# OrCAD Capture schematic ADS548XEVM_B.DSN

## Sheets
1 SH 1 - Analog In: size B; title: ADS548X Evaluation Module; rev: B; note: ADS548XEVM-SCH
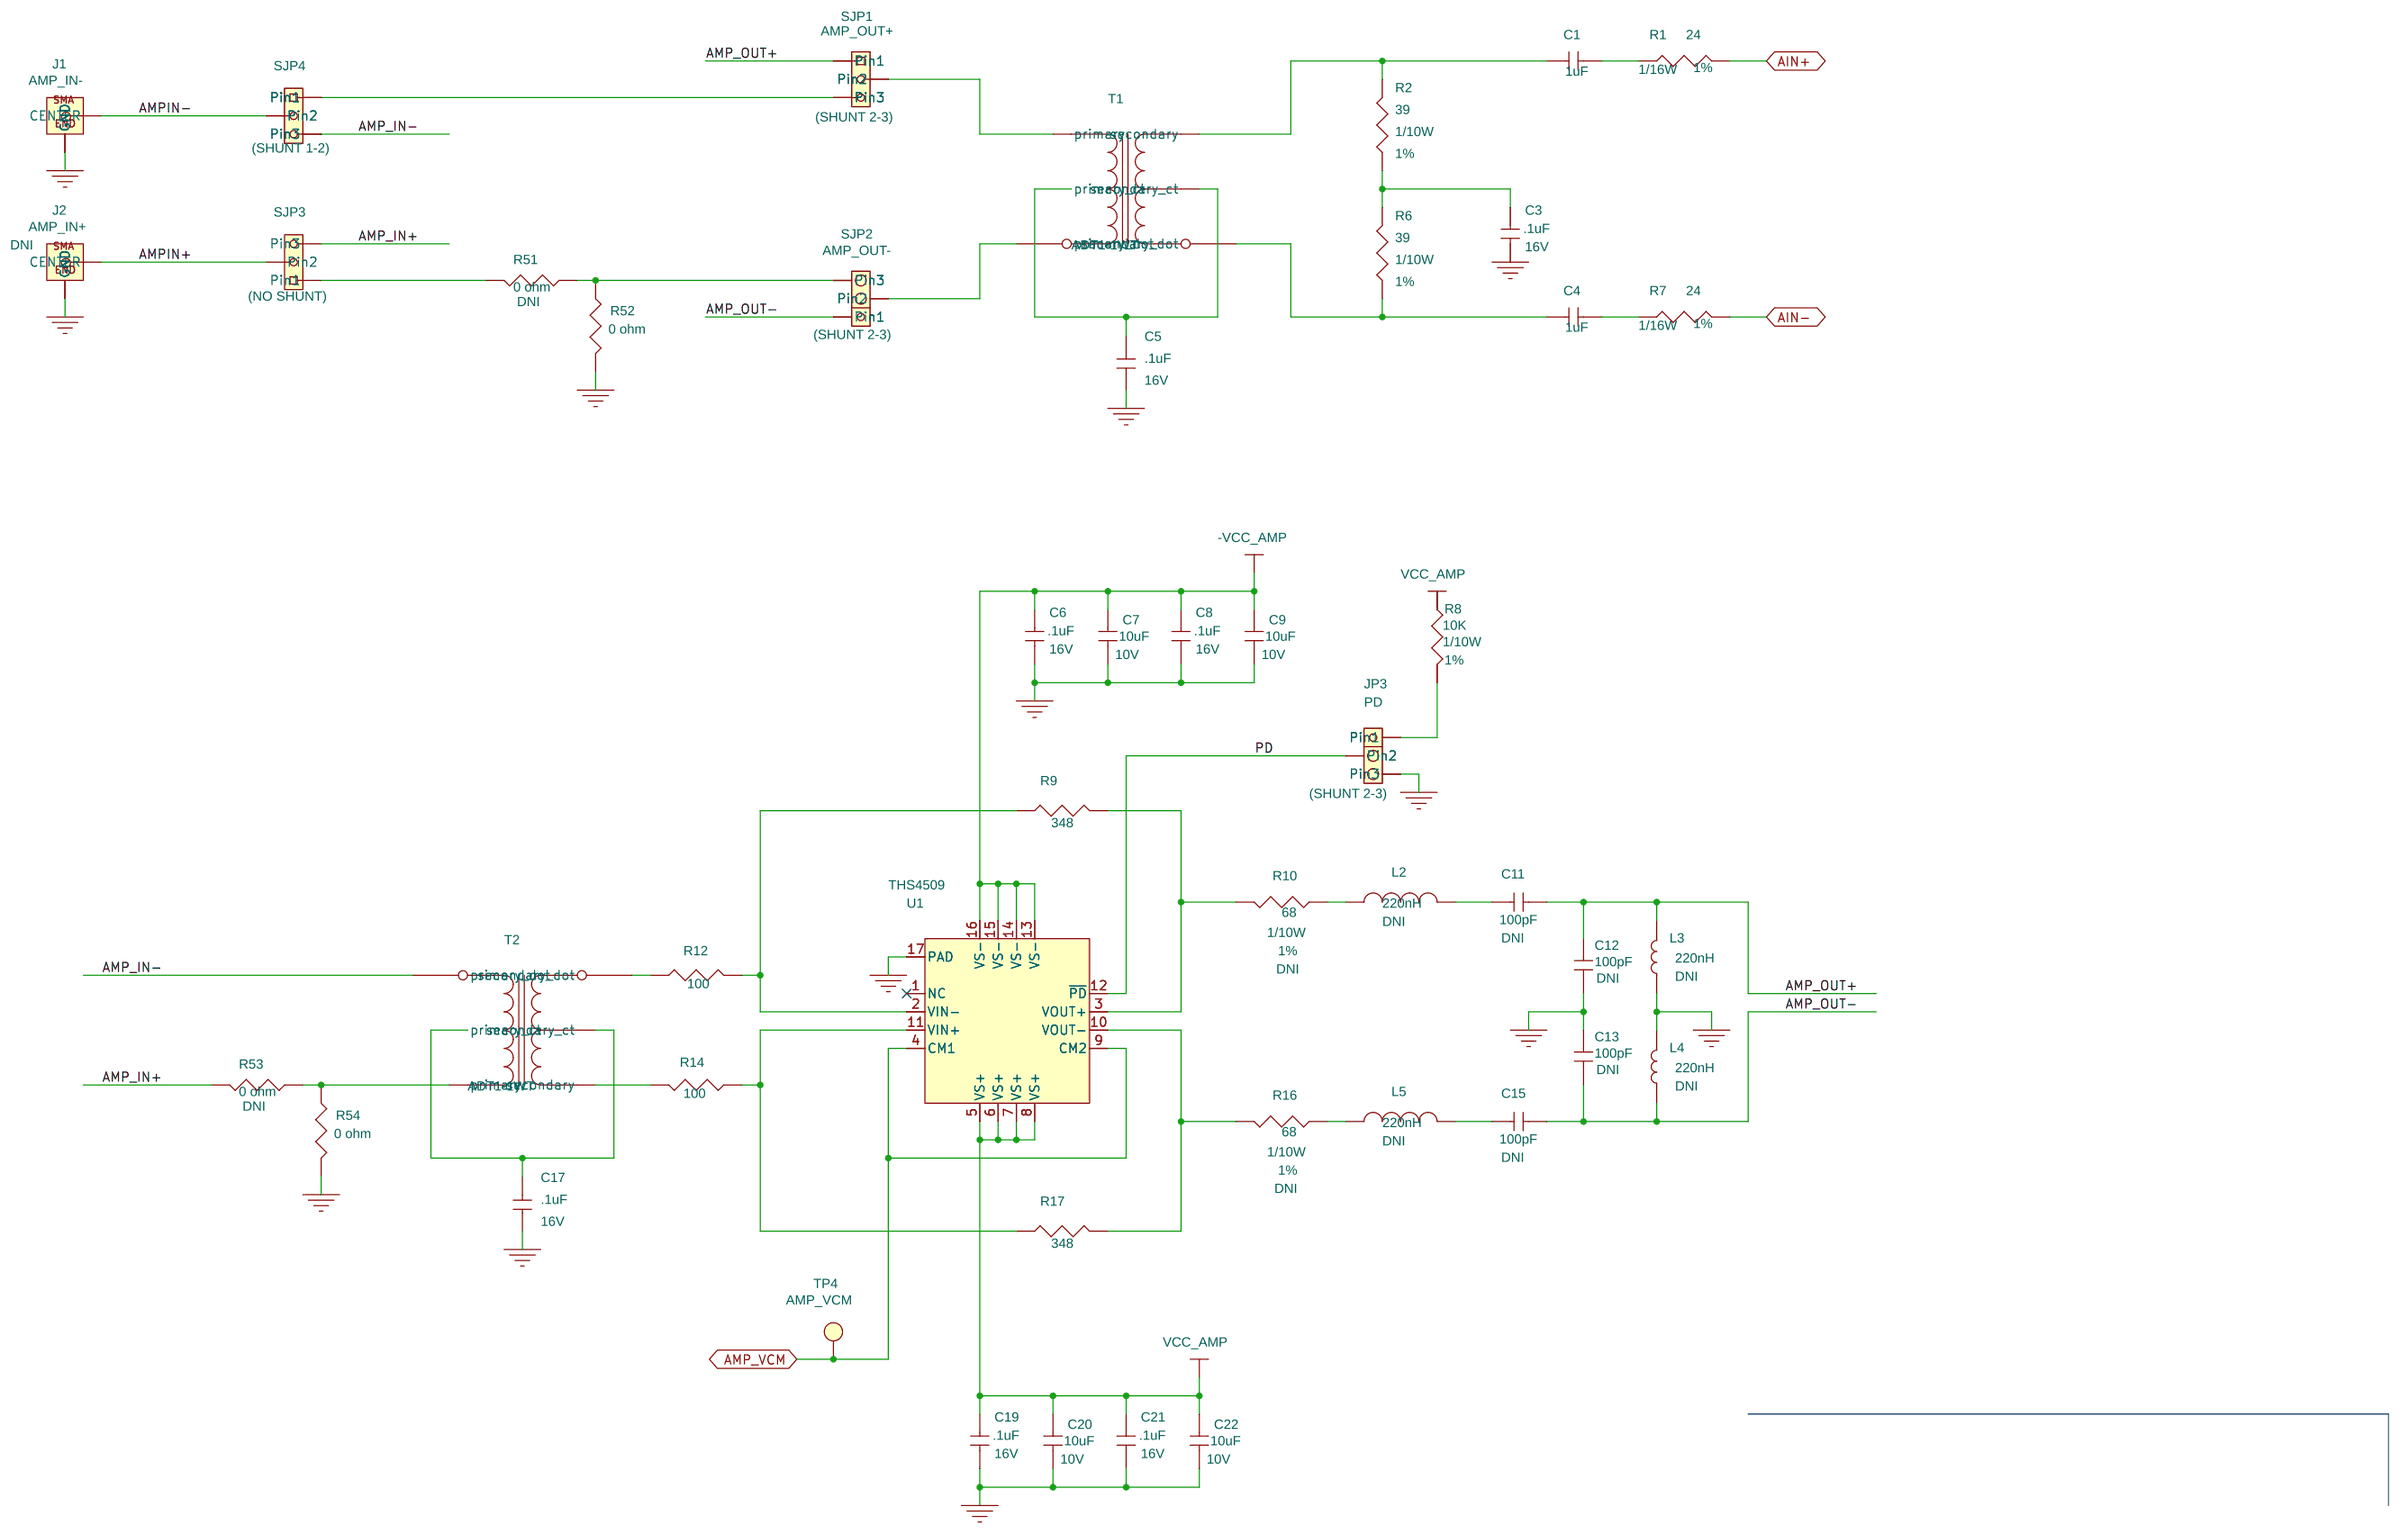
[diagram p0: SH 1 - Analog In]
2 SH 2 - ADC: size B
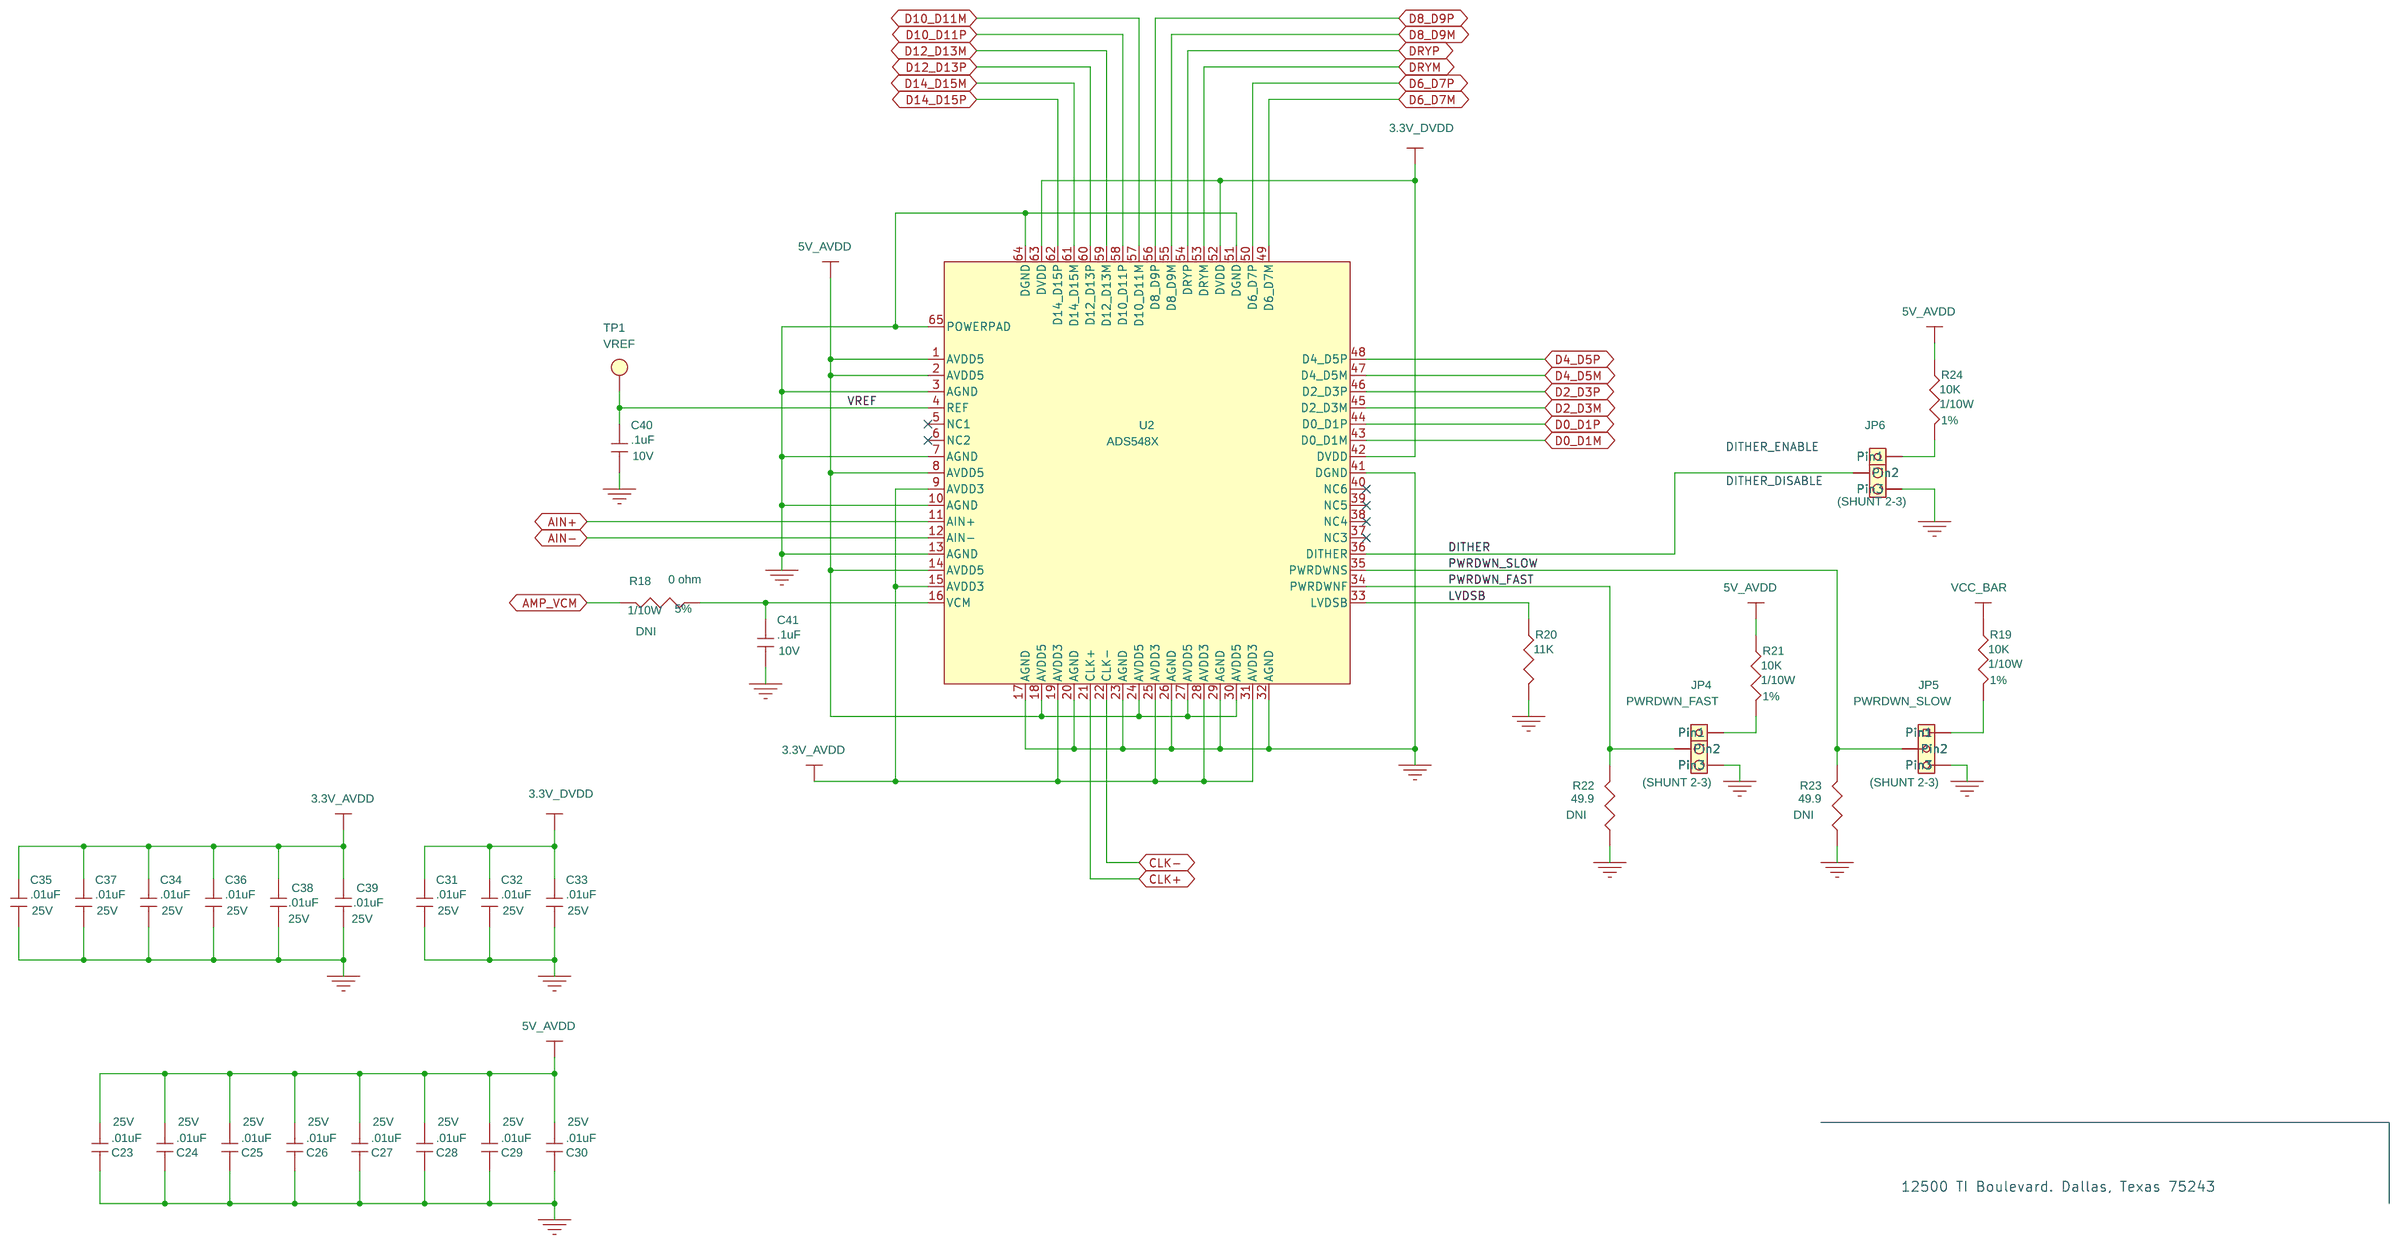
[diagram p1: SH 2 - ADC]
3 SH 3 - Output: size B
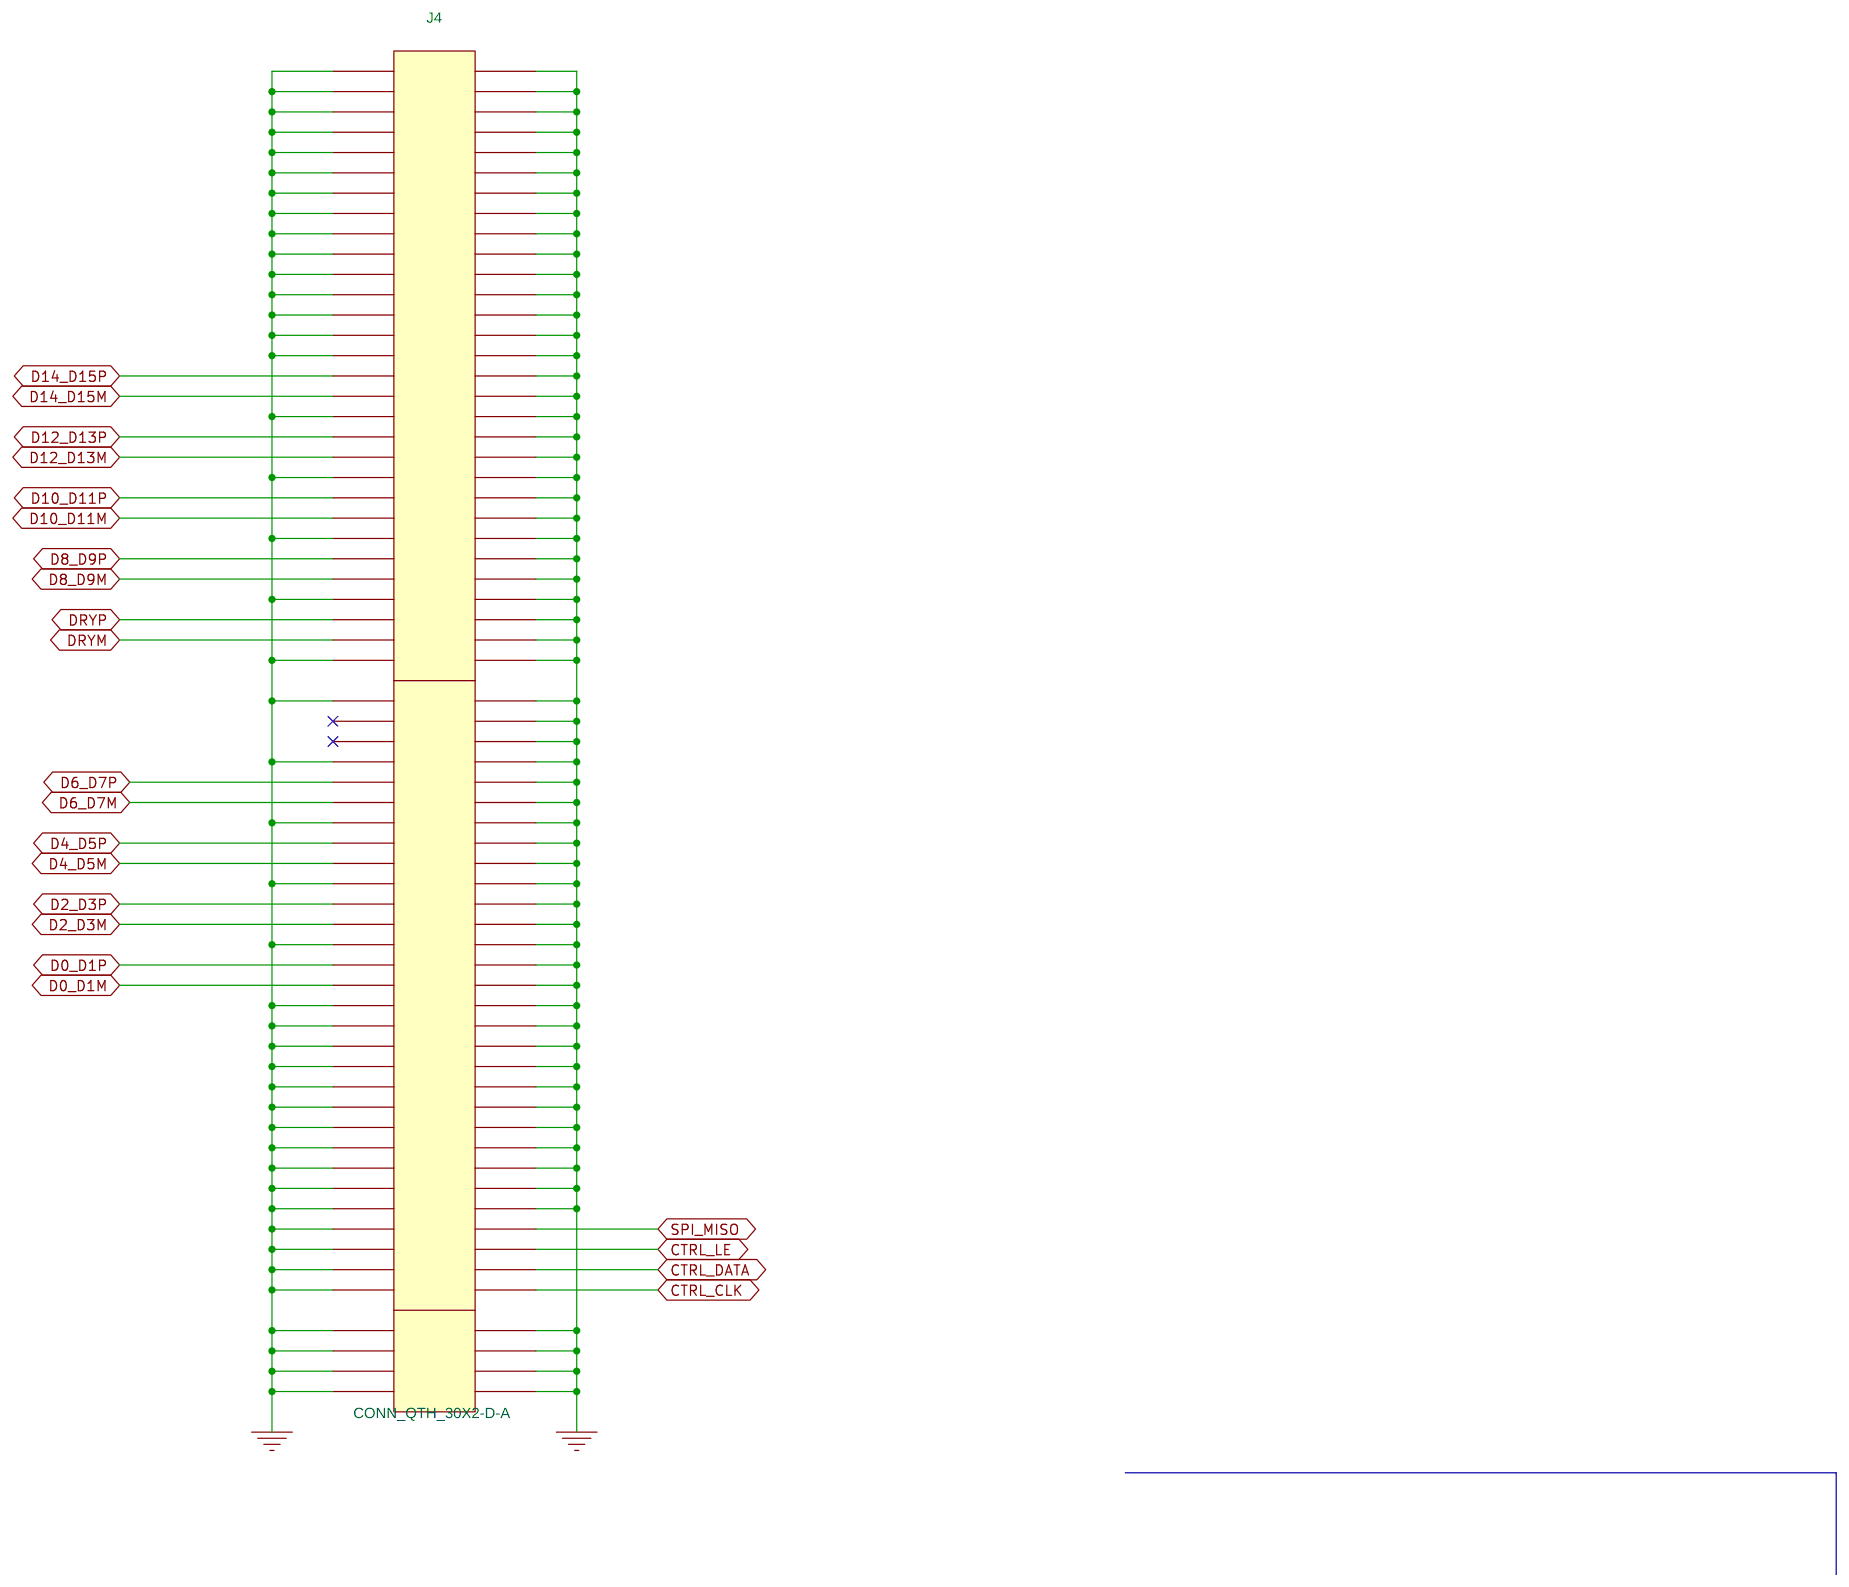
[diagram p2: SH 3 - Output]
4 SH 4 - Power Supplies: size B
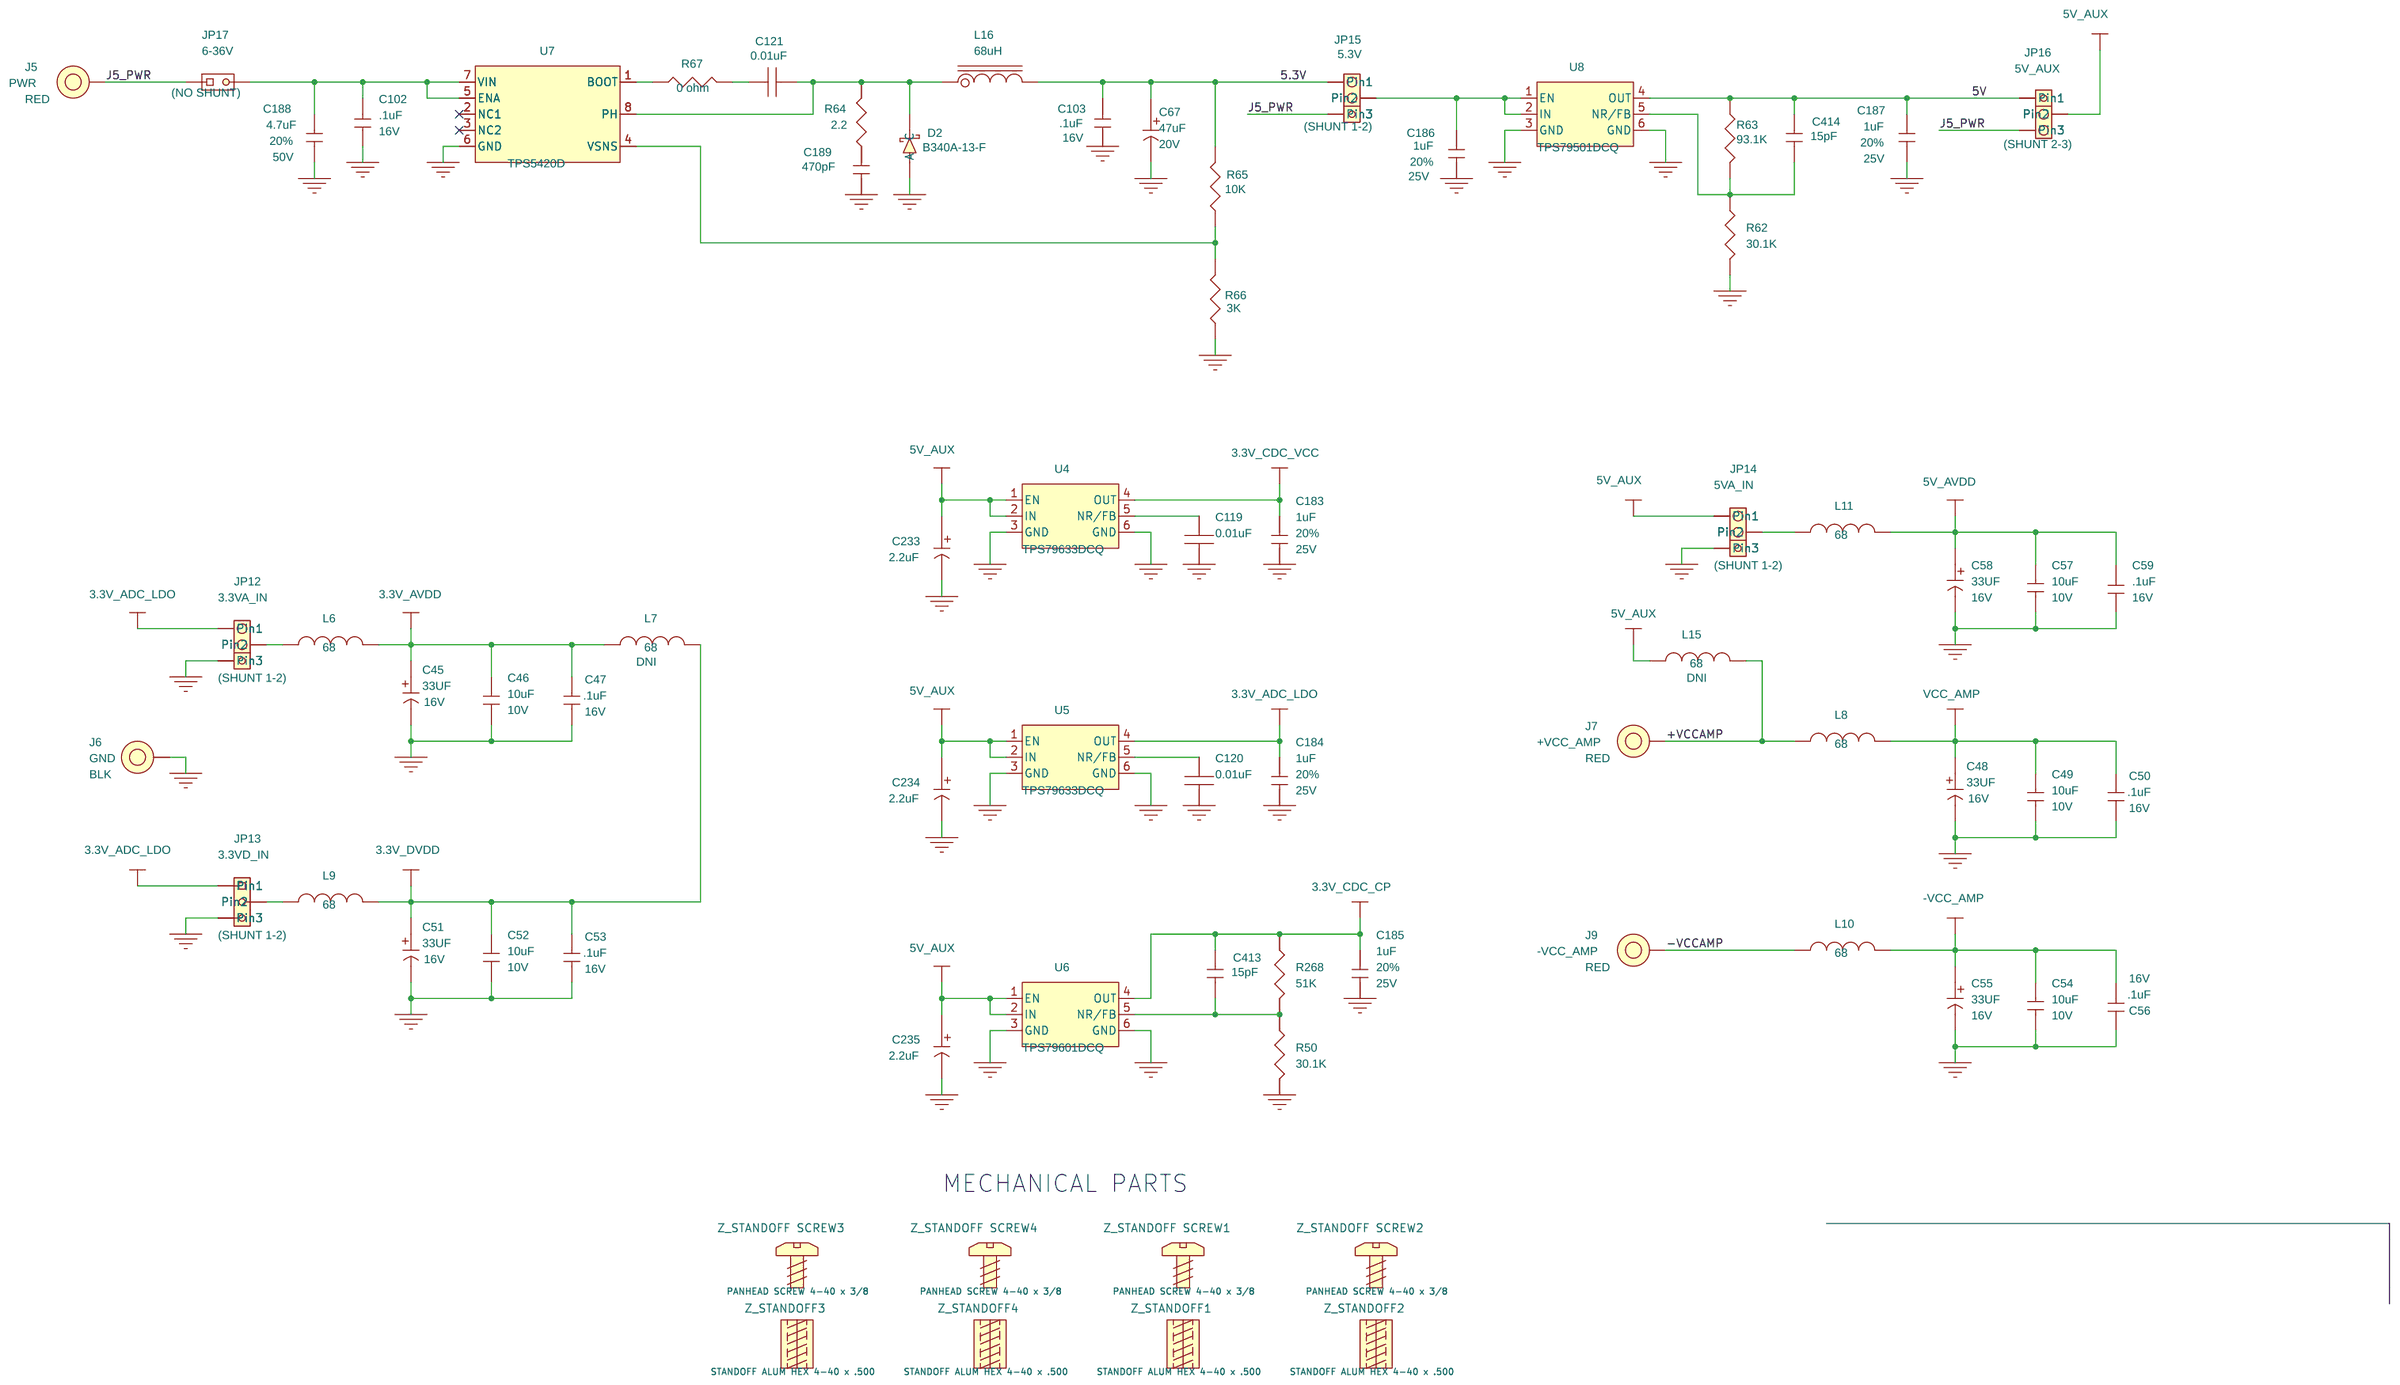
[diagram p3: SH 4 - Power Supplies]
5 SH 5 - Clock In: size B
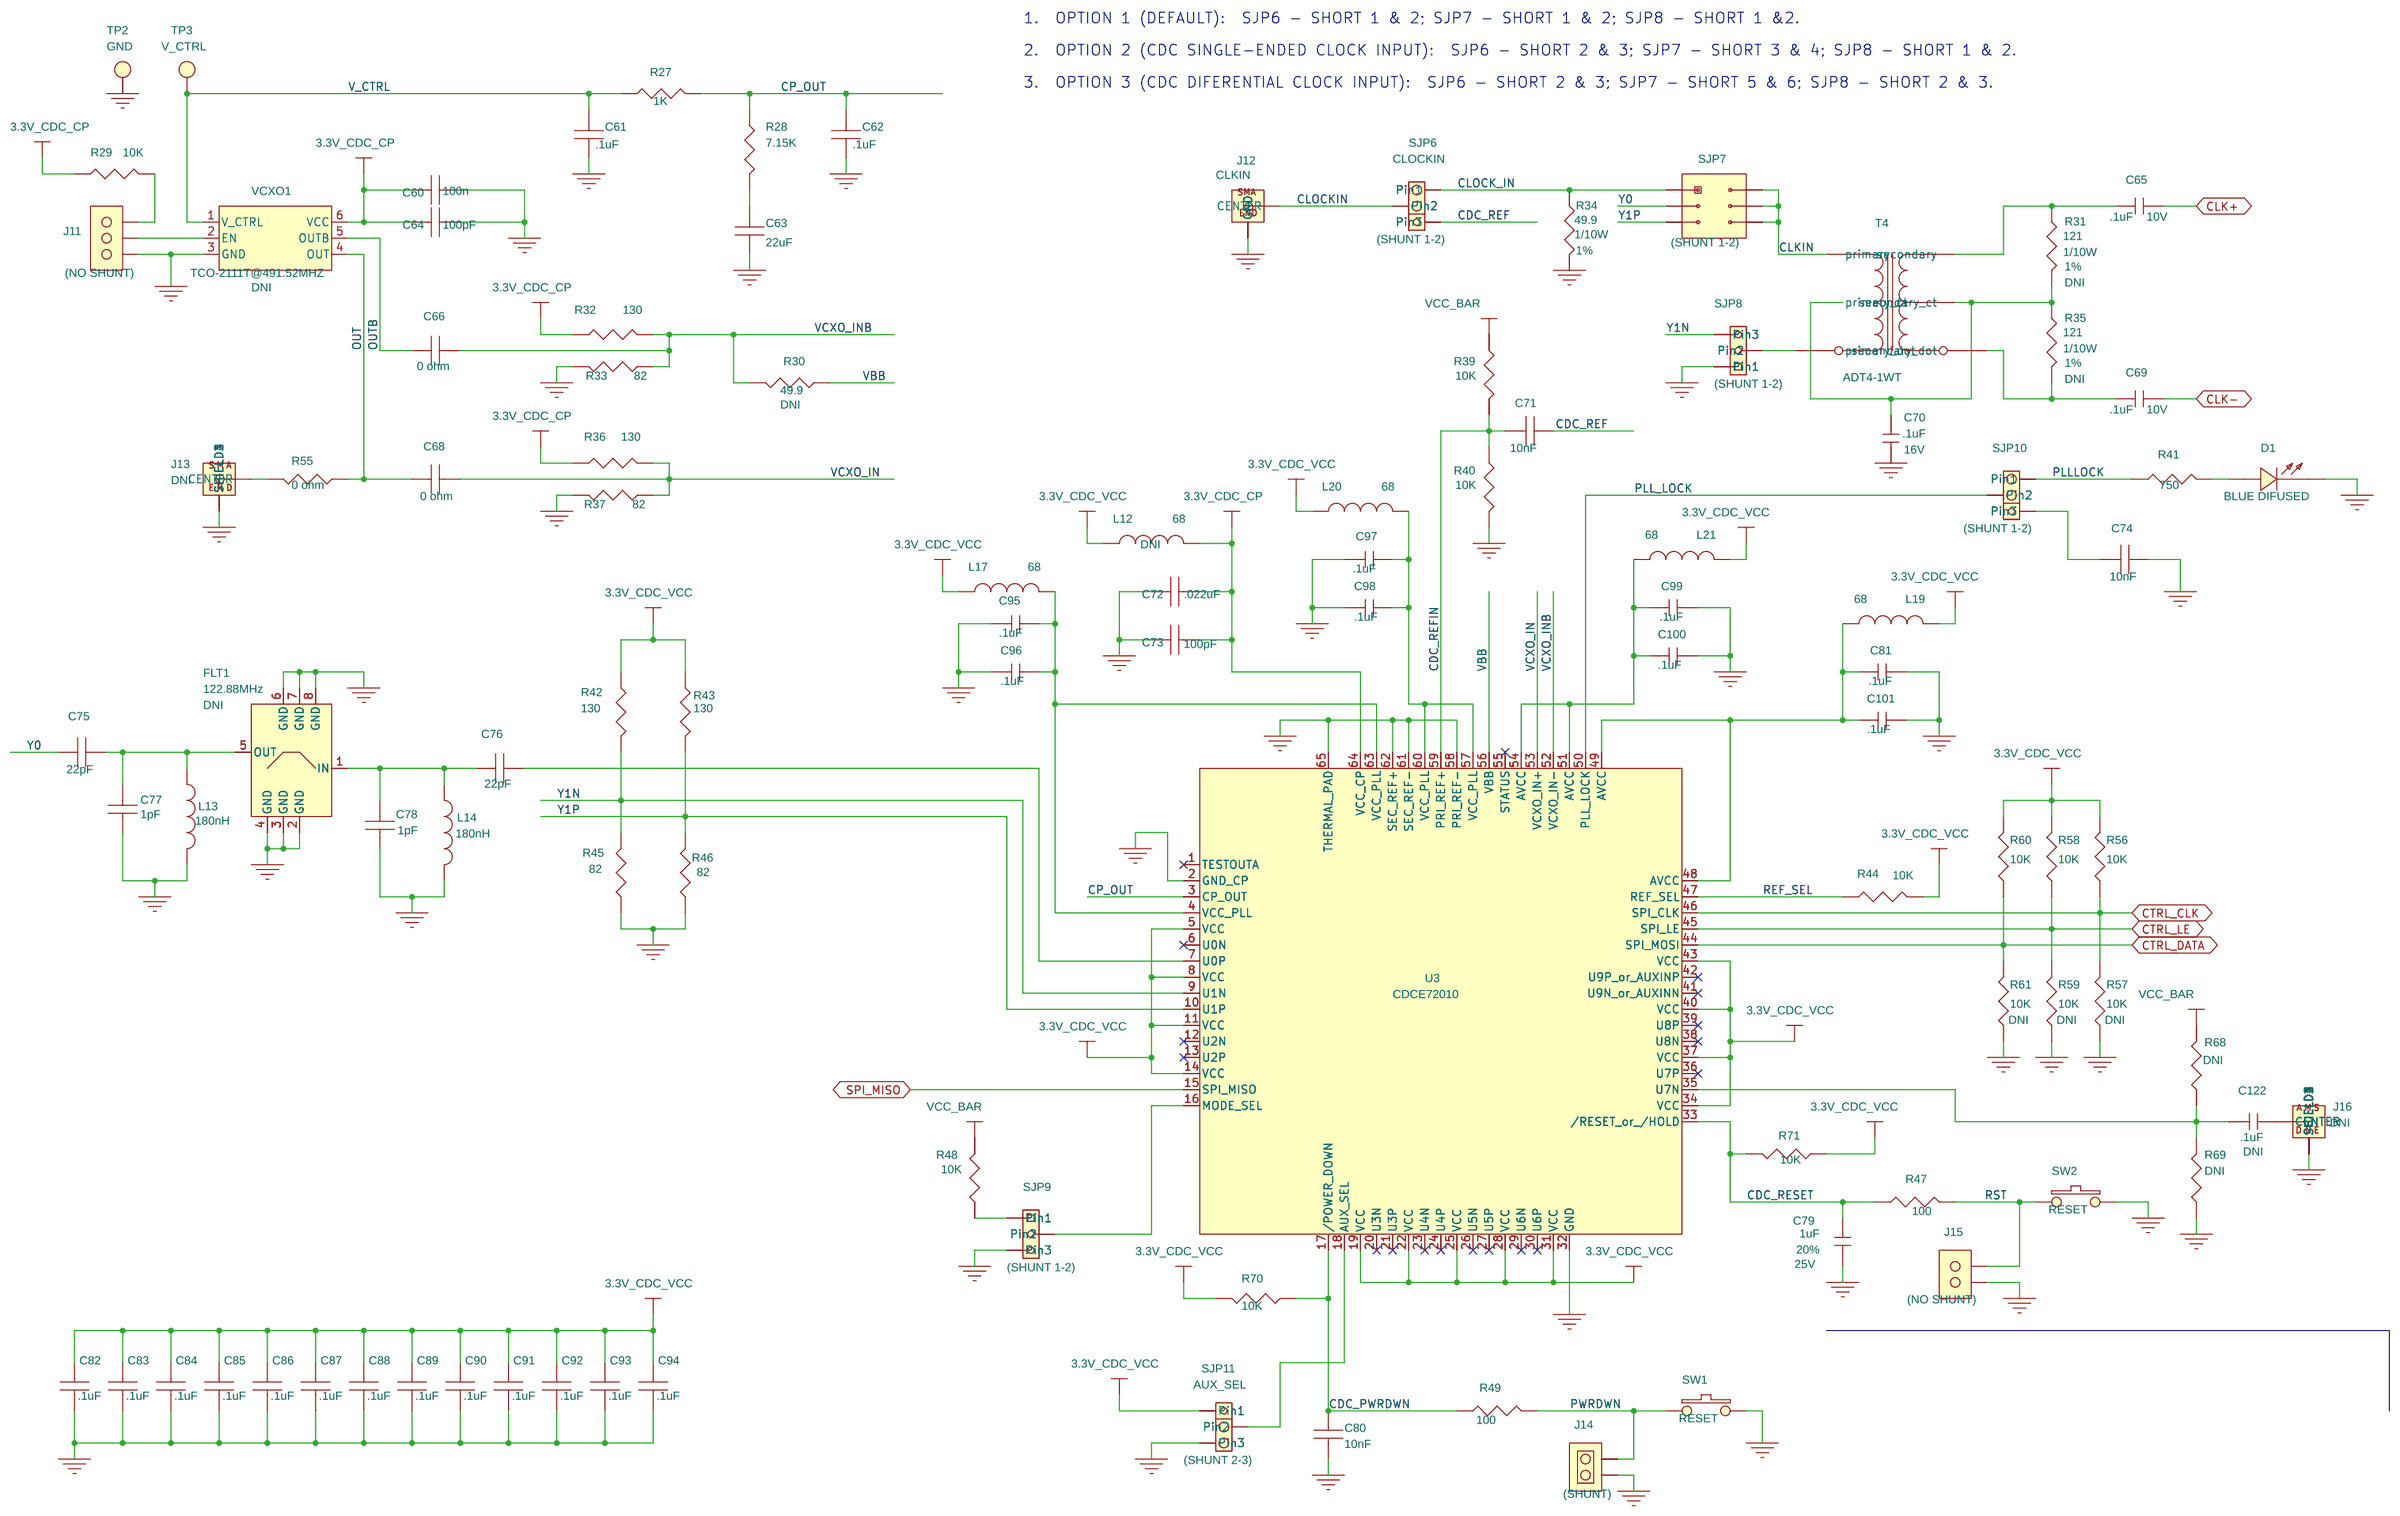
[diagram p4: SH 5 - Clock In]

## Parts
sheet SH 1 - Analog In
C1  1uF  [0603]
C3  .1uF  [0603]
C4  1uF  [0603]
C5  .1uF  [0603]
C6  .1uF  [0603]
C7  10uF  [0805]
C8  .1uF  [0603]
C9  10uF  [0805]
C11  100pF  [0603]
C12  100pF  [0603]
C13  100pF  [0603]
C15  100pF  [0603]
C17  .1uF  [0603]
C19  .1uF  [0603]
C20  10uF  [0805]
C21  .1uF  [0603]
C22  10uF  [0805]
J1  SMA_END_JACK_RND  [SMA_SMEL_250x215]
J2  SMA_END_JACK_RND  [SMA_SMEL_250x215]
JP3  HEADER_1x3_100_430L  [HDR_THVT_1x3_100_M]
L2  220nH  [1206]
L3  220nH  [0603]
L4  220nH  [0603]
L5  220nH  [1206]
R1  24  [0603]
R2  39  [0603]
R6  39  [0603]
R7  24  [0603]
R8  10K  [0603]
R9  348  [0603]
R10  68  [0603]
R12  100  [0603]
R14  100  [0603]
R16  68  [0603]
R17  348  [0603]
R51  0 ohm  [0603]
R52  0 ohm  [0603]
R53  0 ohm  [0603]
R54  0 ohm  [0603]
SJP1  JUMPER_1x3_SMT  [SMD_BRIDGE_1x3_0603]
SJP2  JUMPER_1x3_SMT  [SMD_BRIDGE_1x3_0603]
SJP3  JUMPER_1x3_SMT  [SMD_BRIDGE_1x3_0603]
SJP4  JUMPER_1x3_SMT  [SMD_BRIDGE_1x3_0603]
T1  ADT1-1WT  [TRANS_SMVT_CD542_6]
T2  ADT1-1WT  [TRANS_SMVT_CD542_6]
TP4  Test Point Black  [TP_THVT_060_RND]
U1  THS4509  [QFN_16_124x124_pwrpad]
Z_SH-H1  SHUNT-HEADER
Z_SH-J1  SHUNT-JUMPER-0603
Z_SH-J2  SHUNT-JUMPER-0603
Z_SH-J4  SHUNT-JUMPER-0603
sheet SH 2 - ADC
C23  .01uF  [0402]
C24  .01uF  [0402]
C25  .01uF  [0402]
C26  .01uF  [0402]
C27  .01uF  [0402]
C28  .01uF  [0402]
C29  .01uF  [0402]
C30  .01uF  [0402]
C31  .01uF  [0402]
C32  .01uF  [0402]
C33  .01uF  [0402]
C34  .01uF  [0402]
C35  .01uF  [0402]
C36  .01uF  [0402]
C37  .01uF  [0402]
C38  .01uF  [0402]
C39  .01uF  [0402]
C40  .1uF  [0402]
C41  .1uF  [0402]
JP4  HEADER_1x3_100_430L  [HDR_THVT_1x3_100_M]
JP5  HEADER_1x3_100_430L  [HDR_THVT_1x3_100_M]
JP6  HEADER_1x3_100_430L  [HDR_THVT_1x3_100_M]
R18  0 ohm  [0603]
R19  10K  [0603]
R20  11K  [0603]
R21  10K  [0603]
R22  49.9  [0603]
R23  49.9  [0603]
R24  10K  [0603]
TP1  TP_THVT_060_RND-WHT  [TP_THVT_060_RND]
U2  ADS548X  [QFN64]
Z_SH-H2  SHUNT-HEADER
Z_SH-H3  SHUNT-HEADER
Z_SH-H8  SHUNT-HEADER
sheet SH 3 - Output
J4  CONN_QTH_30X2-D-A  [conn_QTH_30X2-D-A]
sheet SH 4 - Power Supplies
C45  33UF  [TANT_B]
C46  10uF  [0805]
C47  .1uF  [0603]
C48  33UF  [TANT_B]
C49  10uF  [0805]
C50  .1uF  [0603]
C51  33UF  [TANT_B]
C52  10uF  [0805]
C53  .1uF  [0603]
C54  10uF  [0805]
C55  33UF  [TANT_B]
C56  .1uF  [0603]
C57  10uF  [0805]
C58  33UF  [TANT_B]
C59  .1uF  [0603]
C67  47uF  [TANT_E]
C102  .1uF  [0603]
C103  .1uF  [0603]
C119  0.01uF  [0402]
C120  0.01uF  [0402]
C121  0.01uF  [0402]
C183  1uF  [0603]
C184  1uF  [0603]
C185  1uF  [0603]
C186  1uF  [0603]
C187  1uF  [0603]
C188  4.7uF  [1206]
C189  470pF  [0603]
C233  2.2uF  [1206]
C234  2.2uF  [1206]
C235  2.2uF  [1206]
C413  15pF  [0402]
C414  15pF  [0402]
D2  B340A-13-F  [DIODE_SM_DO_214AC]
J5  RED  [JACK_THVT_BANANA_500DIA]
J6  BLK  [JACK_THVT_BANANA_500DIA]
J7  RED  [JACK_THVT_BANANA_500DIA]
J9  RED  [JACK_THVT_BANANA_500DIA]
JP12  HEADER_1x3_100_430L  [HDR_THVT_1x3_100_M]
JP13  HEADER_1x3_100_430L  [HDR_THVT_1x3_100_M]
JP14  HEADER_1x3_100_430L  [HDR_THVT_1x3_100_M]
JP15  HEADER_1x3_100_430L  [HDR_THVT_1x3_100_M]
JP16  HEADER_1x3_100_430L  [HDR_THVT_1x3_100_M]
JP17  HEADER_1x2_100_430L  [HDR_THVT_1x2_100_M]
L6  68  [1206]
L7  68  [1206]
L8  68  [1206]
L9  68  [1206]
L10  68  [1206]
L11  68  [1206]
L15  68  [1206]
L16  68uH  [IND_SM_MSS1038]
R50  30.1K  [0603]
R62  30.1K  [0603]
R63  93.1K  [0603]
R64  2.2  [0603]
R65  10K  [0603]
R66  3K  [0603]
R67  0 ohm  [0603]
R268  51K  [0402]
U4  TPS79633DCQ  [SOT_223_6_TG]
U5  TPS79633DCQ  [SOT_223_6_TG]
U6  TPS79601DCQ  [SOT_223_6_TG]
U7  TPS5420D  [SOIC_8_197x157_50]
U8  TPS79501DCQ  [SOT_223_6_TG]
Z_SH-H4  SHUNT-HEADER
Z_SH-H5  SHUNT-HEADER
Z_SH-H6  SHUNT-HEADER
Z_SH-H9  SHUNT-HEADER
Z_SH-H10  SHUNT-HEADER
Z_STANDOFF1  STANDOFF ALUM HEX 4-40 x .500
Z_STANDOFF2  STANDOFF ALUM HEX 4-40 x .500
Z_STANDOFF3  STANDOFF ALUM HEX 4-40 x .500
Z_STANDOFF4  STANDOFF ALUM HEX 4-40 x .500
Z_STANDOFF SCREW1  PANHEAD SCREW 4-40 x 3/8
Z_STANDOFF SCREW2  PANHEAD SCREW 4-40 x 3/8
Z_STANDOFF SCREW3  PANHEAD SCREW 4-40 x 3/8
Z_STANDOFF SCREW4  PANHEAD SCREW 4-40 x 3/8
sheet SH 5 - Clock In
C60  100n  [0603]
C61  .1uF  [0603]
C62  .1uF  [0603]
C63  22uF  [0805]
C64  100pF  [0603]
C65  .1uF  [0402]
C66  0 ohm  [0603]
C68  0 ohm  [0603]
C69  .1uF  [0402]
C70  .1uF  [0603]
C71  10nF  [0603]
C72  .022uF  [0402]
C73  100pF  [0603]
C74  10nF  [0603]
C75  22pF  [0603]
C76  22pF  [0603]
C77  1pF  [0603]
C78  1pF  [0603]
C79  1uF  [0603]
C80  10nF  [0603]
C81  .1uF  [0201]
C82  .1uF  [0201]
C83  .1uF  [0201]
C84  .1uF  [0201]
C85  .1uF  [0201]
C86  .1uF  [0201]
C87  .1uF  [0201]
C88  .1uF  [0201]
C89  .1uF  [0201]
C90  .1uF  [0201]
C91  .1uF  [0201]
C92  .1uF  [0201]
C93  .1uF  [0201]
C94  .1uF  [0201]
C95  .1uF  [0201]
C96  .1uF  [0201]
C97  .1uF  [0201]
C98  .1uF  [0201]
C99  .1uF  [0201]
C100  .1uF  [0201]
C101  .1uF  [0201]
C122  .1uF  [0402]
D1  BLUE DIFUSED  [DIODE_SM_HSMN_C170]
FLT1  122.88MHz  [FILTER_8_SM_150x150]
J11  HMTSW-103-07-G-S-.240  [HDR_THVT_1x3_100_M]
J12  SMA_END_JACK_RND  [SMA_SMEL_250x215]
J13  TI_SILKTEXT  [SMA_THVT_320x320]
J14  HMTSW-102-07-G-S-.240  [HDR_THVT_1x2_100_M]
J15  HMTSW-102-07-G-S-.240  [HDR_THVT_1x2_100_M]
J16  TI_SILKTEXT  [SMA_THVT_320x320]
L12  68  [1206]
L13  180nH  [0603]
L14  180nH  [0603]
L17  68  [1206]
L19  68  [1206]
L20  68  [1206]
L21  68  [1206]
R27  1K  [0603]
R28  7.15K  [0603]
R29  10K  [0603]
R30  49.9  [0603]
R31  121  [0603]
R32  130  [0603]
R33  82  [0603]
R34  49.9  [0603]
R35  121  [0603]
R36  130  [0603]
R37  82  [0603]
R39  10K  [0603]
R40  10K  [0603]
R41  750  [0603]
R42  130  [0603]
R43  130  [0603]
R44  10K  [0603]
R45  82  [0603]
R46  82  [0603]
R47  100  [0603]
R48  10K  [0603]
R49  100  [0603]
R55  0 ohm  [0603]
R56  10K  [0603]
R57  10K  [0603]
R58  10K  [0603]
R59  10K  [0603]
R60  10K  [0603]
R61  10K  [0603]
R68  10K  [0603]
R69  10K  [0603]
R70  10K  [0603]
R71  10K  [0603]
SJP6  JUMPER_1x3_SMT  [SMD_BRIDGE_1x3_0603]
SJP7  JUMPER_3X2_SMT  [SMD_BRIDGE_2x3_0603]
SJP8  JUMPER_1x3_SMT  [SMD_BRIDGE_1x3_0603]
SJP9  JUMPER_1x3_SMT  [SMD_BRIDGE_1x3_0603]
SJP10  JUMPER_1x3_SMT  [SMD_BRIDGE_1x3_0603]
SJP11  JUMPER_1x3_SMT  [SMD_BRIDGE_1x3_0603]
SW1  RESET  [SW_THVT_SPST_PTS635SL43]
SW2  RESET  [SW_THVT_SPST_PTS635SL43]
T4  ADT4-1WT  [TRANS_SMVT_CD542_6]
TP2  TP_THVT_060_RND-WHT  [TP_THVT_060_RND]
TP3  TP_THVT_060_RND-WHT  [TP_THVT_060_RND]
U3  CDCE72010  [QFN64]
VCXO1  TCO-2111T@491.52MHZ  [VCXO_6_CUSTOM2]
Z_SH-H7  SHUNT-HEADER
Z_SH-J5  SHUNT-JUMPER-0603
Z_SH-J6  SHUNT-JUMPER-0603
Z_SH-J7  SHUNT-JUMPER-0603
Z_SH-J8  SHUNT-JUMPER-0603
Z_SH-J9  SHUNT-JUMPER-0603
Z_SH-J10  SHUNT-JUMPER-0603

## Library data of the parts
C1 C4 = CAP0603: Manufacturer: Panasonic; Mfr_Name: Panasonic; Mfr_Part_Number: ECJ-1VB1C105K; PART_NUMBER: ECJ-1VB1A105K; TOL: 10%; Voltage: 10V
C3 C5 C6 C17 C19 C21 = CAP0603: Manufacturer: Panasonic; Mfr_Name: Panasonic; Mfr_Part_Number: ECJ-1VB1C104K; PART_NUMBER: ECJ-1VB1C104K; TOL: 10%; Voltage: 16V
C7 C9 C20 C22 C46 C49 C52 C54 C57 = CAP0201: Manufacturer: Panasonic; Mfr_Name: Panasonic; Mfr_Part_Number: ECJ-4YB1C106K; PART_NUMBER: ECJ-2FB1A106K; TOL: 10%; VOLTAGE: 10V
C8 = CAP0603: Manufacturer: Panasonic; Mfr_Name: Panasonic; Mfr_Part_Number: ECJ-1VB1C104K; PART_NUMBER: ECJ-1VB1C104K; TOL: 10%; Voltage: 16V; Wattage: 1/10W
C11-C13 C15 = CAP0603: Mfr_Name: Murata; Mfr_Part_Number: GQM1885C1H101JB01D_DNI; Note: DNI
J1 = SMA-END_JACK_142-0711-821_ROUND: TI_Silktext: AMP_IN-
J2 = SMA-END_JACK_142-0711-821_ROUND: Mfr_Part_Number: 142-0711-821_DNI; Note: DNI; TI_Silktext: AMP_IN+
JP3 = JUMPER_1x3_100: Note: (SHUNT 2-3); TI_Silktext: PD
L2 L5 = IND1206: Manufacturer: API Delavan Inc; Mfr_Name: Coilcraft; Mfr_Part_Number: 1206CS-221X-LB_DNI; Note: DNI
L3 L4 = IND0603: Mfr_Name: Coilcraft; Mfr_Part_Number: 0603CS-R22X-LU_DNI; Note: DNI; TOL: 2%
R1 R7 = RES0603: Manufacturer: Panasonic; Mfr_Name: Panasonic; Mfr_Part_Number: ERJ-3GEYJ240V; PART_NUMBER: ERJ-3GEYJ240V; TOL: 1%; Wattage: 1/16W
R2 R6 = RES0603: Manufacturer: Panasonic; Mfr_Name: Panasonic; Mfr_Part_Number: RC0603FR-0739RL; TOL: 1%; Wattage: 1/10W
R8 R19 R21 R24 = RES0603: Manufacturer: Panasonic; Mfr_Name: Panasonic; Mfr_Part_Number: ERJ-3EKF1002V; PART_NUMBER: ERJ-3EKF1002V; TOL: 1%; Wattage: 1/10W
R9 R17 = R: Manufacturer: Panasonic; PART_NUMBER: ERJ-3EKF3480V; TOL: 1%; Wattage: 1/10W
R10 R16 = RES0603: Manufacturer: Panasonic; Mfr_Name: Panasonic; Mfr_Part_Number: ERA-3AEB680V_DNI; Note: DNI; PART_NUMBER: ERA-3AEB680V; TOL: 1%; Wattage: 1/10W
R12 R14 = R: Manufacturer: Panasonic; PART_NUMBER: ERJ-3EKF1000V; TOL: 1%; Wattage: 1/10W
R51 R53 = R: CLASS: DISCRETE; GROUP: NOT INSTALLED; Manufacturer: DALE; Note: DNI; PART_NUMBER: CRCW06030000Z0EA_DNI; TOL: 5%; Wattage: 1/10W
R52 R54 R55 R67 = R: CLASS: DISCRETE; GROUP: NOT INSTALLED; Manufacturer: DALE; PART_NUMBER: CRCW06030000Z0EA; TOL: 5%; Wattage: 1/10W
SJP1 = SMD_JUMPER_0: Note: (SHUNT 2-3); TI_Silktext: AMP_OUT+
SJP2 = SMD_JUMPER_0: Note: (SHUNT 2-3); TI_Silktext: AMP_OUT-
SJP3 = SMD_JUMPER_0: Note: (NO SHUNT)
SJP4 = SMD_JUMPER_0: Note: (SHUNT 1-2)
T1 T2 = XFMR_6_ADT4-1WT: Manufacturer: Mini Circuits
TP4 = T_POINT_R: Manufacturer: Keystone; PART_NUMBER: 5001; TI_Silktext: AMP_VCM
U1 = THS4509_1: Manufacturer: TI; Note: TI Supplied; PART_NUMBER: THS4509RGTT
Z_SH-H1-Z_SH-H6 Z_SH-H8-Z_SH-H10 = SHUNT-HEADER
Z_SH-J1 Z_SH-J2 Z_SH-J4-Z_SH-J6 Z_SH-J8-Z_SH-J10 = SHUNT-JUMPER-0603
C23-C37 = CAP0402: Manufacturer: Panasonic; Mfr_Name: Panasonic; Mfr_Part_Number: ECJ-ZEB1A103K; PART_NUMBER: ECJ-0EB1E103K; TOL: +/-10%; Voltage: 25V
C38 C39 = CAP0201: Manufacturer: Panasonic; Mfr_Name: Panasonic; Mfr_Part_Number: ECJ-4YB1C106K; PART_NUMBER: ECJ-0EB1E103K; TOL: 10%; VOLTAGE: 25V
C40 C41 C65 C69 = CAP0402: Manufacturer: Panasonic; Mfr_Name: Panasonic; Mfr_Part_Number: ECJ-0EF1E104Z; PART_NUMBER: ECJ-0EB1A104K; TOL: 10%; Voltage: 10V
JP4 = JUMPER_1x3_100: Note: (SHUNT 2-3); TI_Silktext: PWRDWN_FAST
JP5 = JUMPER_1x3_100: Note: (SHUNT 2-3); TI_Silktext: PWRDWN_SLOW
JP6 = JUMPER_1x3_100: Note: (SHUNT 2-3); TI_Silktext: TI_Silktext
R18 = RES0805: Manufacturer: Panasonic; Mfr_Name: Panasonic; Mfr_Part_Number: ERJ-3GEY0R00V; Note: DNI; PART_NUMBER: ERJ-3GEY0R00V; TOL: 5%; Wattage: 1/10W
R20 = RES0603: Manufacturer: Panasonic; Mfr_Name: Panasonic; Mfr_Part_Number: ERJ-3EKF1102V; PART_NUMBER: ERJ-3EKF1102V; TOL: 1%; Wattage: 1/10W
R22 R23 R30 = RES0402: GROUP: Not Installed; Manufacturer: Panasonic; Mfr_Name: Panasonic; Mfr_Part_Number: ERJ-3EKF49R9V_DNI; Note: DNI; PART_NUMBER: ERJ-3EKF49R9V_DNI; TOL: 1%; Wattage: 1/10W
TP1 = TP_THVT_060_RND-WHT: TI_SILKTEXT: VREF
U2 = ENZO_8: Manufacturer: TI; Note: TI Supplied
J4 = SAMTEC_CONN_30X2-D-A: Manufacturer: Samtec; PART_NUMBER: QTH-060-02-F-D-A
C45 C48 C51 C55 C58 = CAP_POL-B: Manufacturer: AVX; Mfr_Name: Panasonic; Mfr_Part_Number: ECS-T1AX336R; PART_NUMBER: TPSB336K016R0350; TOL: 10%; Voltage: 16V
C47 C50 C53 C56 C59 C70 C102 C103 = CAP0603: Manufacturer: Panasonic; Mfr_Name: Panasosnic; Mfr_Part_Number: ECJ-1VB1C104K; PART_NUMBER: ECJ-1VB1C104K; TOL: 10%; Voltage: 16V
C67 = CAP_POL-B: Manufacturer: AVX; Mfr_Name: AVX; Mfr_Part_Number: TPSE476M020R0150; PART_NUMBER: TPSE476M020R0150; TOL: 10%; Voltage: 20V
C119-C121 = CAPACITOR_NP_4: CAP, CERAMIC, 0.01uF, 0402, 10%, 25VDC, X7R; Mfr_Name: Panasonic; Mfr_Part_Number: ECJ-0EB1E103K; TOL: 10%
C79 C183-C187 = CAP_NP_0: Mfr_Name: Panasonic; Mfr_Part_Number: ECJ-1V41E105M; TOL: 20%; VOLTAGE: 25V
C188 = CAP_NP_0: Mfr_Name: Murata; Mfr_Part_Number: GRM31CF51H475ZA01L; TOL: 20%; VOLTAGE: 50V
C189 = CAP_NP_0: Mfr_Name: Murata; Mfr_Part_Number: GRM188R71H471MA01D; TOL: 20%; VOLTAGE: 50V
C233-C235 = CAP_POL-B: Mfr_Name: Panasonic; Mfr_Part_Number: ECJ-HVB1A225K
C413 C414 = CAP_NP_0: Mfr_Name: Panasonic; Mfr_Part_Number: ECJ-0EC1H150J; TOL: 5%; VOLTAGE: 50V
D2 = DIODE_B340A-13-F
J5 = BANANA_JACK_RED: Manufacturer: SPC Technology; PART_NUMBER: 845-R; TI_Silktext: PWR
J6 = BANANA_JACK_BLK: Manufacturer: SPC Technology; PART_NUMBER: 845-B; TI_Silktext: GND
J7 = BANANA_JACK_RED: Manufacturer: SPC Technology; PART_NUMBER: 845-R; TI_Silktext: +VCC_AMP
J9 = BANANA_JACK_RED: Manufacturer: SPC Technology; PART_NUMBER: 845-R; TI_Silktext: -VCC_AMP
JP12 = JUMPER_1x3_100: Note: (SHUNT 1-2); TI_Silktext: 3.3VA_IN
JP13 = JUMPER_1x3_100: Note: (SHUNT 1-2); TI_Silktext: 3.3VD_IN
JP14 = JUMPER_1x3_100: Note: (SHUNT 1-2); TI_Silktext: 5VA_IN
JP15 = JUMPER_1x3_100: Note: (SHUNT 1-2); TI_Silktext: 5.3V
JP16 = JUMPER_1x3_100: Note: (SHUNT 2-3); TI_Silktext: 5V_AUX
JP17 = JUMPER_1x2_100: Note: (NO SHUNT); TI_Silktext: 6-36V
L6 L8-L11 L17 L19-L21 = IND1206: Manufacturer: Panasonic; Mfr_Name: Panasonic; Mfr_Part_Number: EXC-ML32A680U; PART_NUMBER: EXC-ML32A680U
L7 L12 L15 = IND1206: Manufacturer: Panasonic; Mfr_Name: Panasonic; Mfr_Part_Number: EXC-ML32A680U_DNI; Note: DNI; PART_NUMBER: EXC-ML32A680U_DNI
L16 = IND_MSS1038_SERIES
R50 R62 = R_4: Mfr_Name: Panasonic; Mfr_Part_Number: ERJ-3EKF3012V; TOL: 1%; VOLTAGE: 1/10W
R63 = R_4: Mfr_Name: Panasonic; Mfr_Part_Number: ERJ-3EKF9312V; TOL: 1%; VOLTAGE: 1/10W
R64 = R_4: Mfr_Name: Panasonic; Mfr_Part_Number: ERJ-3RQF2R2V; TOL: 1%; VOLTAGE: 1/10W
R29 R39 R40 R44 R48 R56 R58 R60 R65 R70 R71 = R: CLASS: DISCRETE; Manufacturer: DALE; PART_NUMBER: CRCW060310K0FKEA; TOL: 1%; Wattage: 1/10W
R66 = R: CLASS: DISCRETE; Manufacturer: Yageo; PART_NUMBER: RC0603FR-073KL; TOL: 1%; Wattage: 1/10W
R268 = R_4: Mfr_Name: Panasonic; Mfr_Part_Number: ERJ-S02F5102X; TOL: 1%
U4 U5 = TPS79633DCQ_1
U6 = TPS79601DCQ_2
U7 = TPS5420D
U8 = TPS79501DCQ_0
Z_STANDOFF1-Z_STANDOFF4 = STANDOFF
Z_STANDOFF SCREW1-Z_STANDOFF SCREW4 = SCREW-STANDOFF
C60-C62 = CAP_NP: CLASS: DISCRETE; Manufacturer: Panasonic; PART_NUMBER: ECJ-1VB1C104K; TOL: 10%; VOLTAGE: 16V
C63 = CAP_NP: CLASS: DISCRETE; Manufacturer: Panasonic; PART_NUMBER: ECJ-2FB0J226M; TOL: 20%; VOLTAGE: 6.3V
C64 C73 = CAP_NP: CLASS: DISCRETE; Manufacturer: Panasonic; PART_NUMBER: ECJ-1VC1H101J; TOL: 5%; VOLTAGE: 50V
C66 C68 = CAP_NP: CLASS: DISCRETE; Manufacturer: DALE; PART_NUMBER: CRCW06030000Z0EA; TOL: 5%; Wattage: 1/10W
C71 C74 C80 = CAP_NP: CLASS: DISCRETE; Manufacturer: AVX; PART_NUMBER: 06035C103KAZ2A; TOL: 10%; VOLTAGE: 50V
C72 = CAP_NP: CLASS: DISCRETE; Manufacturer: AVX Corporation; PART_NUMBER: 0402YC223KAT2A
C75 C76 = CAP_NP: Manufacturer: AVX; PART_NUMBER: 06033J220GBTTR; TOL: 2%; VOLTAGE: 25V
C77 C78 = CAP_NP: Manufacturer: Murata; PART_NUMBER: GQM1885C2A1R0CB01D; TOL: .25pF; VOLTAGE: 100V
C81 C95-C101 = CAP_NP_0: CLASS: DISCRETE; Manufacturer: Panasonic; PART_NUMBER: ECJ-ZEBFJ104K; TOL: 5%; VOLTAGE: 50V
C82-C94 = CAP_NP: CLASS: DISCRETE; Manufacturer: Panasonic; PART_NUMBER: ECJ-ZEBFJ104K; TOL: 5%; VOLTAGE: 50V
C122 = CAP_NP_0: Mfr_Name: Panasonic; Mfr_Part_Number: ECJ-0EB1C104K_DNI; Note: DNI; TOL: 10%; VOLTAGE: 16V
D1 = LED: Manufacturer: AVAGO; PART_NUMBER: HSMN-C170
FLT1 = TS-38S_0: CLASS: DISCRETE; Manufacturer: Toyocom; Note: DNI; PART_NUMBER: TF2-C2EC1_DNI
J11 = HEADER_1x3_0: Note: (NO SHUNT); TI_SILKTEXT: <TI_SILKTEXT>
J12 = SMA-END_JACK_142-0711-821_ROUND: TI_Silktext: CLKIN
J13 J16 = SMA-END_PLUG_ROUND: Manufacturer: Johmson Components; Mfr_Part_Number: 142-0711-821_DNI; Note: DNI; PART_NUMBER: 142-0701-201
J14 = HEADER_1x2_100: Note: (SHUNT)
J15 = HEADER_1x2_0: Note: (NO SHUNT)
L13 L14 = INDUCTOR: Manufacturer: Panasonic; PART_NUMBER: ELJ-RER18JF3; TOL: 5%
R27 = RES0603: Mfr_Name: Panasonic; Mfr_Part_Number: ERJ-3EKF1001V
R28 = R: CLASS: DISCRETE; Manufacturer: Yageo; PART_NUMBER: RT0603DRD077K15L; TOL: .5%; Wattage: 1/10W
R31 R35 = RES0603: GROUP: Not Installed; Manufacturer: Panasonic; Mfr_Name: Panasonic; Mfr_Part_Number: ERJ-3EKF1210V_DNI; Note: DNI; PART_NUMBER: ERJ-3EKF1210V_DNI; TOL: 1%; Wattage: 1/10W
R32 R36 R42 R43 = RESISTOR: CLASS: DISCRETE; Manufacturer: DALE; PART_NUMBER: CRCW0603130RFKEA; TOL: 1%; Wattage: 1/10W
R33 R37 R45 R46 = RESISTOR: CLASS: DISCRETE; Manufacturer: DALE; PART_NUMBER: CRCW060382R0FKEA; TOL: 1%; Wattage: 1/10W
R34 = RES0603: Manufacturer: Panasonic; Mfr_Name: Panasonic; Mfr_Part_Number: ERJ-3EKF49R9V; PART_NUMBER: ERJ-3EKF49R9V; TOL: 1%; Wattage: 1/10W
R41 = RESISTOR: CLASS: DISCRETE; Manufacturer: DALE; PART_NUMBER: CRCW0603750RFKEA
R47 R49 = RESISTOR: CLASS: DISCRETE; Manufacturer: DALE; PART_NUMBER: CRCW0603100RFKEA; TOL: 1%; Wattage: 1/10W
R57 R59 R61 R68 R69 = R: CLASS: DISCRETE; Manufacturer: DALE; Note: DNI; PART_NUMBER: CRCW060310K0FKEA_DNI; TOL: 1%; Wattage: 1/10W
SJP6 = SMD_JUMPER_1x3: Note: (SHUNT 1-2); TI_Silktext: CLOCKIN
SJP7 = JUMPER_3X2_SMT: Mfr_Name: DNI; Mfr_Part_Number: DNI; Note: (SHUNT 1-2)
SJP8-SJP10 = SMD_JUMPER_1x3: Note: (SHUNT 1-2); TI_Silktext: <TI_Silktext>
SJP11 = SMD_JUMPER_1x3: Note: (SHUNT 2-3); TI_Silktext: AUX_SEL
SW1 SW2 = SPST_PB_KT11P3JM_0: Manufacturer: ITT Industries/C&K Div; PART_NUMBER: PTS635SL43
T4 = XFMR_6_ADT4-1WT: Manufacturer: Mini Circuits; Mfr_Name: Minicircuits
TP2 = TP_THVT_060_RND-WHT: TI_SILKTEXT: GND
TP3 = TP_THVT_060_RND-WHT: TI_SILKTEXT: V_CTRL
U3 = ARES: Manufacturer: TI; Note: TI Supplied
VCXO1 = VCXO_6: CLASS: DISCRETE; Manufacturer: TOYOCOM; Mfr_Name: Toyocom; Mfr_Part_Number: TCO-2111T@491.52MHZ_DNI; Note: DNI
Z_SH-H7 = SHUNT-2PINHEADER
Z_SH-J7 = SHUNT-JUMPER-0603_2

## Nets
3.3V_ADC_LDO: C184.1 JP12.1(Pin1) JP13.1(Pin1) U5.4(OUT)
3.3V_AVDD: C34.1 C35.1 C36.1 C37.1 C38.1 C39.1 C45.1 C46.1 C47.1 L6.2 L7.1 U2.9(AVDD3) U2.15(AVDD3) U2.19(AVDD3) U2.25(AVDD3) U2.28(AVDD3) U2.31(AVDD3)
3.3V_CDC_CP: C60.1 C64.1 C72.2 C73.2 C185.1 C413.1 L12.2 R29.2 R32.2 R36.2 R268.1 U3.64(VCC_CP) U6.4(OUT) VCXO1.6(VCC)
3.3V_CDC_VCC: C82.1 C83.1 C84.1 C85.1 C86.1 C87.1 C88.1 C89.1 C90.1 C91.1 C92.1 C93.1 C94.1 C183.1 L12.1 L17.1 L19.1 L20.1 L21.1 R39.2 R42.1 R43.1 R44.2 R48.2 R56.2 R58.2 R60.2 R68.2 R70.2 R71.2 SJP11.1(Pin1) U3.5(VCC) U3.8(VCC) U3.11(VCC) U3.14(VCC) U3.19(VCC) U3.22(VCC) U3.25(VCC) U3.28(VCC) U3.31(VCC) U3.34(VCC) U3.37(VCC) U3.40(VCC) U3.43(VCC) U4.4(OUT)
3.3V_DVDD: C31.1 C32.1 C33.1 C51.1 C52.1 C53.1 L7.2 L9.2 U2.42(DVDD) U2.52(DVDD) U2.63(DVDD)
5.3V: C67.1 C103.2 JP15.1(Pin1) L16.2 R65.2
5V: C187.1 C414.1 JP16.1(Pin1) R63.2 U8.4(OUT)
5V_AUX: C233.1 C234.1 C235.1 JP14.1(Pin1) JP16.2(Pin2) L15.2 U4.1(EN) U4.2(IN) U5.1(EN) U5.2(IN) U6.1(EN) U6.2(IN)
5V_AVDD: C23.2 C24.2 C25.2 C26.2 C27.2 C28.2 C29.2 C30.2 C57.1 C58.1 C59.2 L11.2 R19.1 R21.1 R24.1 U2.1(AVDD5) U2.2(AVDD5) U2.8(AVDD5) U2.14(AVDD5) U2.18(AVDD5) U2.24(AVDD5) U2.27(AVDD5) U2.30(AVDD5)
+VCCAMP: J7.1 L8.1 L15.1
-VCC_AMP: C6.1 C7.1 C8.1 C9.1 C54.1 C55.1 C56.2 L10.2 U1.13(VS-) U1.14(VS-) U1.15(VS-) U1.16(VS-)
-VCCAMP: J9.1 L10.1
GND: C3.2 C5.1 C6.2 C7.2 C8.2 C9.2 C12.2 C13.1 C17.1 C19.2 C20.2 C21.2 C22.2 C23.1 C24.1 C25.1 C26.1 C27.1 C28.1 C29.1 C30.1 C31.2 C32.2 C33.2 C34.2 C35.2 C36.2 C37.2 C38.2 C39.2 C40.2 C41.2 C45.2 C46.2 C47.2 C48.2 C49.2 C50.2 C51.2 C52.2 C53.2 C54.2 C55.2 C56.1 C57.2 C58.2 C59.1 C60.2 C61.1 C62.1 C63.1 C64.2 C67.2 C70.2 C72.1 C73.1 C74.1 C77.1 C78.1 C79.2 C80.2 C81.2 C82.2 C83.2 C84.2 C85.2 C86.2 C87.2 C88.2 C89.2 C90.2 C91.2 C92.2 C93.2 C94.2 C95.2 C96.2 C97.2 C98.2 C99.2 C100.2 C101.2 C102.1 C103.1 C119.2 C120.2 C183.2 C184.2 C185.2 C186.2 C187.2 C188.2 C189.2 C233.2 C234.2 C235.2 D1.2(CATHODE) D2.1(A) FLT1.2(GND) FLT1.3(GND) FLT1.4(GND) FLT1.6(GND) FLT1.7(GND) FLT1.8(GND) J1.2(GND) J1.3(GND) J1.4(GND) J1.5(GND) J2.2(GND) J2.3(GND) J2.4(GND) J2.5(GND) J4.1 J4.2 J4.3 J4.4 J4.5 J4.6 J4.7 J4.8 J4.9 J4.10 J4.11 J4.12 J4.13 J4.14 J4.15 J4.16 J4.17 J4.18 J4.19 J4.20 J4.21 J4.22 J4.23 J4.24 J4.25 J4.26 J4.27 J4.28 J4.29 J4.30 J4.31 J4.33 J4.35 J4.36 J4.37 J4.39 J4.41 J4.42 J4.43 J4.45 J4.47 J4.48 J4.49 J4.51 J4.53 J4.54 J4.55 J4.57 J4.59 J4.60 J4.61 J4.62 J4.63 J4.65 J4.67 J4.68 J4.69 J4.71 J4.73 J4.74 J4.75 J4.77 J4.79 J4.80 J4.81 J4.83 J4.85 J4.86 J4.87 J4.89 J4.91 J4.92 J4.93 J4.94 J4.95 J4.96 J4.97 J4.98 J4.99 J4.100 J4.101 J4.102 J4.103 J4.104 J4.105 J4.106 J4.107 J4.108 J4.109 J4.110 J4.111 J4.112 J4.114 J4.116 J4.118 J4.120 J4.G1 J4.G2 J4.G3 J4.G4 J4.G5 J4.G6 J4.G7 J4.G8 J6.1 J11.3 J12.2(GND) J12.3(GND) J12.4(GND) J12.5(GND) J13.2(SHIELD3) J13.3(SHIELD4) J13.4(SHIELD1) J13.5(SHIELD2) J14.2 J15.2 J16.2(SHIELD3) J16.3(SHIELD4) J16.4(SHIELD1) J16.5(SHIELD2) JP3.3(Pin3) JP4.3(Pin3) JP5.3(Pin3) JP6.3(Pin3) JP12.3(Pin3) JP13.3(Pin3) JP14.3(Pin3) L3.1 L4.2 L13.2 L14.2 R20.2 R22.2 R23.2 R33.2 R34.2 R37.2 R40.1 R45.2 R46.2 R50.1 R52.2 R54.2 R57.1 R59.1 R61.1 R62.1 R66.1 R69.1 SJP8.1(Pin1) SJP9.3(Pin3) SJP11.3(Pin3) SW1.2 SW2.2 TP2.1(TP) U1.17(PAD) U2.3(AGND) U2.7(AGND) U2.10(AGND) U2.13(AGND) U2.17(AGND) U2.20(AGND) U2.23(AGND) U2.26(AGND) U2.29(AGND) U2.32(AGND) U2.41(DGND) U2.51(DGND) U2.64(DGND) U2.65(POWERPAD) U3.2(GND_CP) U3.32(GND) U3.58(PRI_REF-) U3.61(SEC_REF-) U3.62(SEC_REF+) U3.65(THERMAL_PAD) U4.3(GND) U4.6(GND) U5.3(GND) U5.6(GND) U6.3(GND) U6.6(GND) U7.6(GND) U8.3(GND) U8.6(GND) VCXO1.3(GND)
VCC_AMP: C19.1 C20.1 C21.1 C22.1 C48.1 C49.1 C50.1 L8.2 R8.1 U1.5(VS+) U1.6(VS+) U1.7(VS+) U1.8(VS+)
AIN+: R1.2 U2.11(AIN+)
AIN-: R7.2 U2.12(AIN-)
AMP_IN+: R53.2 SJP3.3(Pin3)
AMP_IN-: SJP4.3(Pin3) T2.3(primary_dot)
AMP_OUT+: C11.2 C12.1 L3.2 SJP1.1(Pin1)
AMP_OUT-: C13.2 C15.2 L4.1 SJP2.1(Pin1)
AMP_VCM: R18.1 TP4.1(TP) U1.4(CM1) U1.9(CM2)
AMPIN+: J2.1(CENTER) SJP3.2(Pin2)
AMPIN-: J1.1(CENTER) SJP4.2(Pin2)
CDC_PWRDWN: C80.1 R49.2 R70.1 U3.17(/POWER_DOWN)
CDC_REF: C71.1 SJP6.3(Pin3)
CDC_REFIN: C71.2 R39.1 R40.2 U3.59(PRI_REF+)
CDC_RESET: C79.1 R47.1 R71.1 U3.33(/RESET_or_/HOLD)
CLK+: C65.2 U2.21(CLK+)
CLK-: C69.2 U2.22(CLK-)
CLKIN: SJP7.2 SJP7.4 SJP7.6 T4.1(primary)
CLOCK_IN: R34.1 SJP6.1(Pin1) SJP7.1
CLOCKIN: J12.1(CENTER) SJP6.2(Pin2)
CP_OUT: C62.2 R27.2 R28.2 U3.3(CP_OUT)
CTRL_CLK: J4.119 R56.1 R57.2 U3.46(SPI_CLK)
CTRL_DATA: J4.117 R60.1 R61.2 U3.44(SPI_MOSI)
CTRL_LE: J4.115 R58.1 R59.2 U3.45(SPI_LE)
D0_D1M: J4.90 U2.43(D0_D1M)
D0_D1P: J4.88 U2.44(D0_D1P)
D2_D3M: J4.84 U2.45(D2_D3M)
D2_D3P: J4.82 U2.46(D2_D3P)
D4_D5M: J4.78 U2.47(D4_D5M)
D4_D5P: J4.76 U2.48(D4_D5P)
D6_D7M: J4.72 U2.49(D6_D7M)
D6_D7P: J4.70 U2.50(D6_D7P)
D8_D9M: J4.52 U2.55(D8_D9M)
D8_D9P: J4.50 U2.56(D8_D9P)
D10_D11M: J4.46 U2.57(D10_D11M)
D10_D11P: J4.44 U2.58(D10_D11P)
D12_D13M: J4.40 U2.59(D12_D13M)
D12_D13P: J4.38 U2.60(D12_D13P)
D14_D15M: J4.34 U2.61(D14_D15M)
D14_D15P: J4.32 U2.62(D14_D15P)
DITHER: JP6.2(Pin2) U2.36(DITHER)
DRYM: J4.58 U2.53(DRYM)
DRYP: J4.56 U2.54(DRYP)
J5_PWR: J5.1 JP15.3(Pin3) JP16.3(Pin3) JP17.1
LVDSB: R20.1 U2.33(LVDSB)
OUT: C68.1 R55.1 VCXO1.4(OUT)
OUTB: C66.1 VCXO1.5(OUTB)
PD: JP3.2(Pin2) U1.12(~{PD})
PLL_LOCK: SJP10.2(Pin2) U3.50(PLL_LOCK)
PLLLOCK: R41.2 SJP10.1(Pin1)
PWRDWN: J14.1 R49.1 SW1.1
PWRDWN_FAST: JP4.2(Pin2) R22.1 U2.34(PWRDWNF)
PWRDWN_SLOW: JP5.2(Pin2) R23.1 U2.35(PWRDWNS)
REF_SEL: R44.1 U3.47(REF_SEL)
RST: J15.1 R47.2 SW2.1
SPI_MISO: J4.113 U3.15(SPI_MISO)
V_CTRL: C61.2 R27.1 TP3.1(TP) VCXO1.1(V_CTRL)
VBB: R30.1 U3.56(VBB)
VCXO_IN: C68.2 R36.1 R37.1 U3.53(VCXO_IN+)
VCXO_INB: C66.2 R30.2 R32.1 R33.1 U3.52(VCXO_IN-)
VREF: C40.1 TP1.1(TP) U2.4(REF)
Y0: C75.1 SJP7.3
Y1N: R42.2 R45.1 SJP8.3(Pin3) U3.9(U1N)
Y1P: R43.2 R46.1 SJP7.5 U3.10(U1P)
N840990: JP14.2(Pin2) L11.1
N1283130: JP4.1(Pin1) R21.2
N1283662: JP5.1(Pin1) R19.2
N7817251: C1.2 R1.1
N7817255: C1.1 R2.2 T1.6(secondary)
N7817305: C5.2 T1.2(primary_ct) T1.5(secondary_ct)
N7817373: SJP1.2(Pin2) T1.1(primary)
N7817411: C4.1 R6.1 T1.4(secondary_dot)
N7817443: C3.1 R2.1 R6.2
N7817501: SJP2.2(Pin2) T1.3(primary_dot)
N7817683: C4.2 R7.1
N7869749: R9.1 R12.2 U1.2(VIN-)
N7876568: R14.2 R17.1 U1.11(VIN+)
N7891704: R9.2 R10.2 U1.3(VOUT+)
N7895234: R16.2 R17.2 U1.10(VOUT-)
N7989911: JP3.1(Pin1) R8.2
N8074988: L2.1 R10.1
N8077138: C11.1 L2.2
N8081368: C15.1 L5.2
N8081478: L5.1 R16.1
N10992825: C41.1 R18.2 U2.16(VCM)
N11942302: C63.2 R28.1
N11942314: C97.1 C98.1 L20.2 U3.57(VCC_PLL) U3.60(VCC_PLL)
N11942322: C99.1 C100.1 L21.2 U3.51(AVCC) U3.54(AVCC)
N11942704: C95.1 C96.1 L17.2 U3.4(VCC_PLL) U3.63(VCC_PLL)
N11942986: SJP9.2(Pin2) U3.16(MODE_SEL)
N11944036: R48.1 SJP9.1(Pin1)
N11944640: C70.1 R31.2 R35.1 T4.2(primary_ct) T4.5(secondary_ct)
N11944644: C69.1 R35.2 T4.4(secondary_dot)
N11944730: C65.1 R31.1 T4.6(secondary)
N11944968: C81.1 C101.1 L19.2 U3.48(AVCC) U3.49(AVCC)
N11945768: J11.2 VCXO1.2(EN)
N12059293: J11.1 R29.1
N12462125: C75.2 C77.2 FLT1.5(OUT) L13.1
N12462201: C76.1 C78.2 FLT1.1(IN) L14.1
N12462429: C76.2 U3.7(U0P)
N12585663: JP12.2(Pin2) L6.1
N12596555: C119.1 U4.5(NR/FB)
N12601673: C120.1 U5.5(NR/FB)
N16120501: C413.2 R50.2 R268.2 U6.5(NR/FB)
N16137056: JP13.2(Pin2) L9.1
N16233186: SJP1.3(Pin3) SJP4.1(Pin1)
N16236131: R51.1 R52.1 SJP2.3(Pin3)
N16246718: C17.2 T2.2(primary_ct) T2.5(secondary_ct)
N16246802: R53.1 R54.1 T2.1(primary)
N16249025: R12.1 T2.4(secondary_dot)
N16249528: R14.1 T2.6(secondary)
N16262729: R51.2 SJP3.1(Pin1)
N16321121: SJP8.2(Pin2) T4.3(primary_dot)
N16569642: C74.2 SJP10.3(Pin3)
N16571989: D1.1(ANODE) R41.1
N16772002: JP6.1(Pin1) R24.2
N16784753: J13.1(CENTER) R55.2
N16813901: SJP11.2(Pin2) U3.18(AUX_SEL)
N16862878: C186.1 JP15.2(Pin2) U8.1(EN) U8.2(IN)
N16883561: C102.2 C188.1 JP17.2 U7.5(ENA) U7.7(VIN)
N16890469: C414.2 R62.2 R63.1 U8.5(NR/FB)
N16920126: C121.2 D2.2(C) L16.1 R64.2 U7.8(PH)
N16948070: R65.1 R66.2 U7.4(VSNS)
N17014791: C189.1 R64.1
N17094031: R67.2 U7.1(BOOT)
N17095752: C121.1 R67.1
N17113241: C122.2 R68.1 R69.2 U3.35(U7N)
N17540177: C122.1 J16.1(CENTER)

Not connected (* = marked no-connect by the designer): J4 64* 66*; U1 1(NC)*; U2 5(NC1)* 6(NC2)* 37(NC3)* 38(NC4)* 39(NC5)* 40(NC6)*; U3 1(TESTOUTA)* 6(U0N)* 12(U2N)* 13(U2P)* 20(U3N)* 21(U3P)* 23(U4N)* 24(U4P)* 26(U5N)* 27(U5P)* 29(U6N)* 30(U6P)* 36(U7P)* 38(U8N)* 39(U8P)* 41(U9N_or_AUXINN)* 42(U9P_or_AUXINP)* 55(STATUS)*; U7 2(NC1)* 3(NC2)*

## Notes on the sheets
sheet 2
- DITHER_ENABLE
- DITHER_DISABLE
- 12500 TI Boulevard. Dallas, Texas 75243
sheet 4
- MECHANICAL PARTS
sheet 5
- 1.  OPTION 1 (DEFAULT):  SJP6 - SHORT 1 & 2; SJP7 - SHORT 1 & 2; SJP8 - SHORT 1 &2.
- 2.  OPTION 2 (CDC SINGLE-ENDED CLOCK INPUT):  SJP6 - SHORT 2 & 3; SJP7 - SHORT 3 & 4; SJP8 - SHORT 1 & 2.
- 3.  OPTION 3 (CDC DIFERENTIAL CLOCK INPUT):  SJP6 - SHORT 2 & 3; SJP7 - SHORT 5 & 6; SJP8 - SHORT 2 & 3.
